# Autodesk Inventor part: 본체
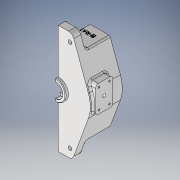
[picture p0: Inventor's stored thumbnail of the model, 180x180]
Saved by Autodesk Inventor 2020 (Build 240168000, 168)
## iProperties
Created: 2023-11
Part Number: 본체
Material: 일반
Document SubType Name: Modeling
Designer: CAD14
Density: 1 g/cm^3
Appearance: 기본값
Mass: 579.61 g
Surface Area: 721.297 cm^2
Volume: 579.61 cm^3
Author: CAD14
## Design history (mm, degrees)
sketch "스케치1"
  geometry: L1 (-24.317, -94)-(24.317, -94); L2 (24.317, -94)-(24.317, 94); L3 (24.317, 94)-(-24.317, 94); L4 (-24.317, 94)-(-24.317, -94); L5 (-24.317, -94)-(24.317, 94); L6 (24.317, -94)-(-24.317, 94); L7 (24.317, 94)-(51.683, 18.811); L8 (0, 0)-(55, 0); L9 (0, 0)-(0, 55); L10 (-24.317, 94)-(-51.683, 18.811); L11 (24.317, -94)-(51.683, -18.811); L12 (-24.317, -94)-(-51.683, -18.811); L13 (-33.78, -68)-(33.78, -68); L14 (33.78, -68)-(33.78, 68); L15 (33.78, 68)-(-33.78, 68); L16 (-33.78, 68)-(-33.78, -68); L17 (-33.78, -68)-(33.78, 68); L18 (33.78, -68)-(-33.78, 68); C1 r 17.5 at (0, 0); A1 r 55 centre (0, 0) between (51.683, 18.811) and (55, 0); 7 further points
  constraints: 36 end point, 4 midpoint, 4 parallel, 3 horizontal, 3 point on circle, 3 symmetric about line, 2 centre point, 2 coincident, 2 perpendicular, 1 point on line, 1 tangent, 1 vertical
  dimensions: "d0" = 110 diameter of A1; "d1" = 188 distance of L1.end L2.end; "d5" = 136 distance of L14.end L13.end; "d8" = 35 diameter of C1; "d109" = 40 deg angle of L7 L10
extrude "돌출1" new body sketch "스케치1" distance "d3" = 15; taper "d4" = 0 deg
extrude "돌출2" join sketch "스케치1" distance "d6" = 55; taper "d7" = 0 deg
extrude "돌출3" join sketch "스케치1" distance "d9" = 5; taper "d10" = 0 deg
sketch "스케치2"
  geometry: C1 r 40 at (0, 9); C2 r 47.5 at (0, 9); C3 r 43.4 at (0, 9); 1 further point
  constraints: 3 centre point, 1 coincident, 1 vertical alignment
  dimensions: "d11" = 80 diameter of C1; "d12" = 9 distance of point (0, 0) C1.centre; "d13" = 95 diameter of C2; "d16" = 4.1 radial gap between concentric circles of C2 C3
sketch "스케치5"
  geometry: L1 (-14, -5)-(32, -5); L2 (32, -5)-(32, -35); L3 (32, -35)-(-14, -35); L4 (-14, -35)-(-14, -5); L5 (-14, -5)-(32, -35); L6 (32, -5)-(-14, -35); L7 (94, 0)-(18.811, 0) reference; 3 further points
  constraints: 12 end point, 3 midpoint, 2 parallel, 1 horizontal, 1 perpendicular
  dimensions: "d23" = 46 distance of L2.end L3.end; "d24" = 30 distance of L1.end L2.end; "d54" = 9 horizontal distance of point (0, 0) point (9, -20); "d55" = 20 vertical distance of point (9, -20) point (0, 0)
extrude "돌출7" join sketch "스케치5" stored distance "d27" = 118; taper "d28" = 0 deg
extrude "돌출4" cut sketch "스케치2" distance "d14" = 30; taper "d15" = 0 deg
extrude "돌출5" cut sketch "스케치2" distance "d17" = 2.4; taper "d18" = 0 deg
sketch "스케치3"
  geometry: C1 r 10 at (0, -9); 1 further point
  constraints: 1 centre point, 1 coincident
  dimensions: "d19" = 20 diameter of C1
extrude "돌출6" cut sketch "스케치3" distance "d20" = 10; taper "d21" = 0 deg
sketch "스케치4"
  geometry: C1 r 8 at (0, 0); 1 further point
  constraints: 1 centre point, 1 coincident
  dimensions: "d22" = 16 diameter of C1
extrude "돌출8" cut sketch "스케치4" distance "d29" = 11.6; taper "d30" = 0 deg
sketch "스케치6"
  geometry: C1 r 17.5 at (0, 0) reference; 2 further points
  constraints: 1 coincident
hole "구멍1" sketch "스케치6" at (0, 0) diameter "d31" = 25; stored, may be unused: countersink angle "d35" = 90 deg, drill point angle "d37" = 0 deg; dims "d32" = 6, "d33" = 4, "d34" = 2, "d36" = 8.4
sketch "스케치7"
  geometry: L1 (-29, 0)-(29, 0); L2 (-29, 6)-(29, 6); L3 (-29, -6)-(29, -6); L4 (-29, 17)-(29, 17); L5 (0, -9)-(0, 38.035); L6 (-15, 17)-(15, 17); C1 r 24 at (0, -9); A1 r 29 centre (0, 0) between (-28.566, 5) and (28.566, 5); 12 further points
  constraints: 12 end point, 4 point on circle, 3 parallel, 2 centre point, 2 horizontal, 2 midpoint, 1 coincident, 1 vertical, 1 vertical alignment
  dimensions: "d38" = 58 diameter of A1; "d39" = 9 distance of A1.centre point (0, -9); "d40" = 48 diameter of C1; "d45" = 9 distance from line of point (0, -9) L1; "d46" = 6 distance between parallel lines of L1 L2; "d47" = 6 distance between parallel lines of L1 L3; "d48" = 17 distance between parallel lines of L4 L1; "d49" = 30 distance of L6.start L6.end
extrude "돌출10" cut sketch "스케치7" distance "d50" = 12; taper "d51" = 0 deg
fillet "모깎기2" dims "d52" = 2
fillet "모깎기3" dims "d53" = 2
sketch "스케치9"
  geometry: L1 (0, 0)-(20, 0); L2 (20, 0)-(20, 9); L3 (20, 9)-(0, 9); L4 (0, 9)-(0, 0); L5 (11, -8)-(29, -8); L6 (29, -8)-(29, 26); L7 (29, 26)-(11, 26); L8 (11, 26)-(11, -8); L9 (11, -8)-(29, 26); L10 (29, -8)-(11, 26); C1 r 3 at (20, 9)
  constraints: 20 end point, 4 parallel, 2 horizontal, 2 midpoint, 2 perpendicular, 1 centre point, 1 coincident
  dimensions: "d56" = 20 distance of L3.end L2.end; "d57" = 9 distance of L2.end L1.end; "d58" = 6 diameter of C1; "d61" = 18 distance of L7.end L6.end; "d62" = 34 distance of L6.end L5.end
extrude "돌출11" cut sketch "스케치9" stored distance "d59" = 12; taper "d60" = 0 deg
hole "구멍2" sketch "스케치7" diameter "d63" = 3.242; stored, may be unused: countersink angle "d67" = 90 deg, drill point angle "d69" = 118 deg; dims "d64" = 8, "d65" = 4, "d66" = 2, "d68" = 10
hole "구멍3" sketch "스케치9" diameter "d70" = 3.242; stored, may be unused: countersink angle "d74" = 90 deg, drill point angle "d76" = 118 deg; dims "d71" = 8, "d72" = 4, "d73" = 2, "d75" = 10
sketch "스케치10"
  geometry: L1 (-20, -79)-(20, -79); L2 (20, -79)-(20, 79); L3 (20, 79)-(-20, 79); L4 (-20, 79)-(-20, -79); L5 (-20, -79)-(20, 79); L6 (20, -79)-(-20, 79); C1 r 12.5 at (0, 0) reference; 1 further point
  constraints: 12 end point, 2 midpoint, 2 parallel, 1 horizontal, 1 perpendicular
  dimensions: "d77" = 40 distance of L3.end L2.end; "d78" = 158 distance of L2.end L1.end
hole "구멍4" sketch "스케치10" at (-20, -79), (20, -79), (-20, 79), (20, 79) diameter "d79" = 6.6; stored, may be unused: countersink angle "d83" = 90 deg, drill point angle "d85" = 118 deg; dims "d80" = 8, "d81" = 11, "d82" = 6.6, "d84" = 15
sketch "스케치11"
  geometry: L1 (-25, -61)-(25, -61); L2 (25, -61)-(25, 61); L3 (25, 61)-(-25, 61); L4 (-25, 61)-(-25, -61); L5 (-25, -61)-(25, 61); L6 (25, -61)-(-25, 61); C1 r 10 at (0, 0) reference; 1 further point
  constraints: 12 end point, 2 midpoint, 2 parallel, 1 horizontal, 1 perpendicular
  dimensions: "d86" = 50 distance of L3.end L2.end; "d87" = 122 distance of L2.end L1.end
hole "구멍5" sketch "스케치11" at (25, 61), (-25, 61), (-25, -61), (25, -61) diameter "d88" = 4.917; stored, may be unused: countersink angle "d92" = 90 deg, drill point angle "d94" = 118 deg; dims "d89" = 12, "d90" = 11, "d91" = 6.6, "d93" = 14
sketch "스케치12"
  geometry: L1 (12.5, 5)-(12.5, 12.599); L2 (-12.5, 5)-(12.5, 5) reference; L3 (17.5, 5)-(-17.5, 5) reference; L4 (12.5, 5)-(12.5, 4.6); L5 (12.5, -3.4)-(12.5, 5) reference; L6 (12.5, 4.6)-(13.235, 5.873); L7 (12.5, 5)-(12.731, 5); L8 (0, 5)-(0, 2.376); 1 further point
  constraints: 10 end point, 3 point on line, 2 vertical, 1 midpoint
  dimensions: "d97" = 0.4 distance of L1.start L4.end; "d98" = 30 deg angle of L6 L4
revolve "회전1" sketch "스케치12" stored, may be unused: angle "d99" = 90 deg
fillet "모깎기4" dims "d100" = 0.2
fillet "모깎기5" dims "d101" = 0.5
fillet "모깎기6" dims "d102" = 10
fillet "모깎기7" dims "d103" = 5
fillet "모깎기8" dims "d104" = 3
fillet "모깎기9" dims "d105" = 3
sketch "스케치13"
  geometry: L1 (63.358, 0)-(0, 0) reference; L2 (0, 37)-(63.358, 37) reference; 3 further points
  constraints: 1 midpoint, 1 vertical alignment, 1 other
  dimensions: "d113" = 15 distance from line of L2 point (31.679, 22)
feature "엠보싱1" sketch "스케치13" dims "d0" = 110, "d1" = 188, "d5" = 136, "d8" = 35, "d107" = 0.5, "d108" = 0, "d109" = 40 deg
chamfer "모따기1" distance "d110" = 1; stored, may be unused: second distance "d111" = 2, angle "d112" = 45 deg
feature "분할1"
node "솔리드1"
mirror "미러1"
mirror "미러2"
feature "A9D066F2-1C7D-4E18-AEED-F7BC21143FA4" dims "d31" = 25, "d32" = 6, "d33" = 4, "d34" = 2, "d35" = 90 deg, "d36" = 8.4, "d37" = 0
